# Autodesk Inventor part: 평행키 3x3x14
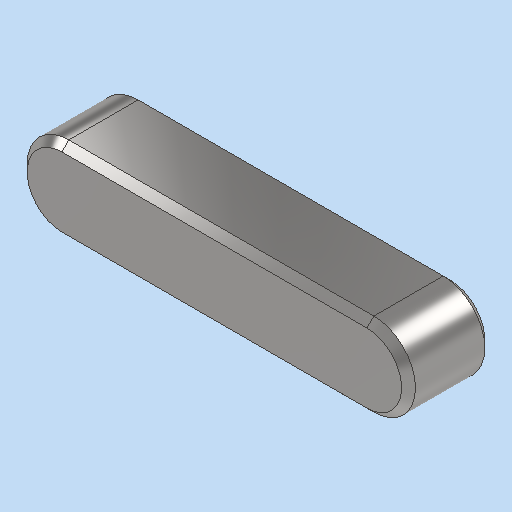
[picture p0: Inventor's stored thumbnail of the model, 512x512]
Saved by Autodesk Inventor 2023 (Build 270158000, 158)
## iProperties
Created: 2024-09
Part Number: 평행키 3x3x14
Material: 강철, 연강
Description: 키 및 해당 키홈
Document SubType Name: Modeling
Designer: asung
Density: 7.85 g/cm^3
Appearance: 기본값
Author: jhkim
Sending System: Autodesk Inventor 2025
Preprocessor: ST-DEVELOPER v20
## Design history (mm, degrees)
feature "Solid1"
node "솔리드1"
